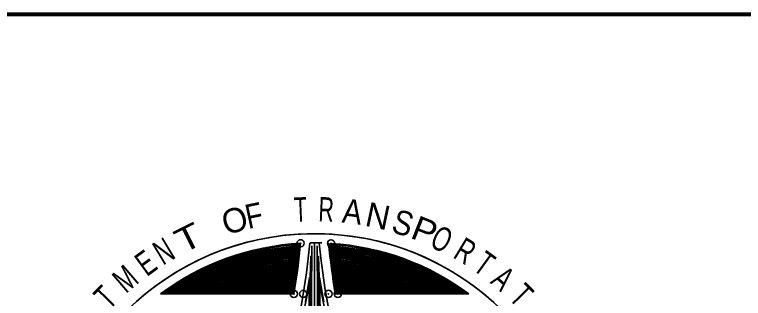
# Model space of a CAD drawing. Extents: x 763.8 to 797.8, y -170.3 to -127.3.
# Drawn here: x 779.152 to 783.061, y -128.791 to -127.265 of the extents above; entities that cross this region are included whole.
import ezdxf
from ezdxf.enums import TextEntityAlignment as Align

# ---------------------------------------------------------------- set-up
doc = ezdxf.new("R2010")
doc.units = 0
doc.header["$LTSCALE"] = 0.077
doc.header["$PDMODE"] = 32
doc.header["$PDSIZE"] = 0.0385
doc.layers.add('1', color=7, linetype='Continuous', lineweight=35)

msp = doc.modelspace()

# ---------------------------------------------------------------- linework, layer by layer
at = {"layer": '1', "lineweight": 80}
msp.add_line((794.76075, -127.26542), (766.76075, -127.26542), dxfattribs=at)
at = {"layer": '1'}
for p, q in [((780.76075, -128.49192), (780.76075, -130.44333)), ((780.6495, -128.76592), (779.93417, -128.76592)), ((780.87192, -128.76592), (781.58725, -128.76592))]:
    msp.add_line(p, q, dxfattribs=at)
for points in [[(779.95233, -128.76325), (780.64367, -128.76075), (780.6815, -128.49958), (780.57933, -128.51033), (780.46733, -128.53008), (780.35692, -128.55892), (780.27125, -128.58775), (780.20117, -128.61408), (780.14183, -128.64625), (780.07592, -128.67842), (780.01992, -128.71708), (779.97375, -128.74433), (779.94575, -128.76408), (779.95975, -128.75992), (780.63867, -128.7575), (780.67742, -128.50617), (780.57933, -128.51775), (780.47475, -128.535), (780.38983, -128.55808), (780.361, -128.563), (780.26875, -128.59517), (780.21025, -128.61658), (780.07842, -128.685), (779.96308, -128.75833), (780.63625, -128.7525), (780.67333, -128.51192), (780.56208, -128.52675), (780.478, -128.53917), (780.36592, -128.56633), (780.21517, -128.6215), (780.08083, -128.68908), (779.97708, -128.75583), (780.63125, -128.75008), (780.66917, -128.51692), (780.48217, -128.54325), (780.37258, -128.57125), (780.22008, -128.62567), (780.08417, -128.694), (779.99025, -128.75342), (780.62633, -128.74592), (780.66508, -128.52183), (780.48375, -128.54817), (780.37092, -128.577), (780.22342, -128.63058), (780.08583, -128.69817), (780.0075, -128.74925), (780.62225, -128.7435), (780.65925, -128.52842), (780.48958, -128.55317), (780.37008, -128.58283), (780.22917, -128.6355), (780.08825, -128.70225), (780.02233, -128.74758), (780.61725, -128.73933), (780.65267, -128.535), (780.49283, -128.55892), (780.37417, -128.58858), (780.23742, -128.63883), (780.09158, -128.708), (780.03717, -128.7435), (780.61317, -128.73525), (780.64858, -128.54242), (780.49775, -128.56383), (780.37917, -128.5935), (780.24233, -128.64292), (780.09483, -128.713), (780.0545, -128.74017), (780.60817, -128.73108), (780.64442, -128.549), (780.50358, -128.56958), (780.38242, -128.59933), (780.24567, -128.64875), (780.0965, -128.71708), (780.07017, -128.73692), (780.60408, -128.727), (780.6395, -128.55558), (780.50358, -128.57542), (780.38658, -128.60508), (780.24892, -128.65367), (780.099, -128.72292), (780.0825, -128.73358), (780.59833, -128.72208), (780.63458, -128.56142), (780.5085, -128.58117), (780.39067, -128.60917), (780.25225, -128.65942), (780.09817, -128.73108), (780.59417, -128.71958), (780.628, -128.56883), (780.51342, -128.58692), (780.3915, -128.61742), (780.2605, -128.66275), (780.11792, -128.72783), (780.59092, -128.71708), (780.62225, -128.57625), (780.52, -128.591), (780.39067, -128.62483), (780.26708, -128.666), (780.13692, -128.7245), (780.58758, -128.71383), (780.61725, -128.58442)], [(781.56917, -128.76325), (780.87783, -128.76075), (780.83992, -128.49958), (780.94208, -128.51033), (781.05417, -128.53008), (781.16458, -128.55892), (781.25025, -128.58775), (781.32025, -128.61408), (781.37967, -128.64625), (781.44558, -128.67842), (781.50158, -128.71708), (781.54775, -128.74433), (781.57575, -128.76408), (781.56175, -128.75992), (780.88275, -128.7575), (780.84408, -128.50617), (780.94208, -128.51775), (781.04675, -128.535), (781.13158, -128.55808), (781.16042, -128.563), (781.25275, -128.59517), (781.31125, -128.61658), (781.44308, -128.685), (781.55842, -128.75833), (780.88525, -128.7525), (780.84817, -128.51192), (780.95942, -128.52675), (781.04342, -128.53917), (781.1555, -128.56633), (781.30625, -128.6215), (781.44058, -128.68908), (781.54442, -128.75583), (780.89017, -128.75008), (780.85225, -128.51692), (781.03933, -128.54325), (781.14892, -128.57125), (781.30133, -128.62567), (781.43725, -128.694), (781.53125, -128.75342), (780.89517, -128.74592), (780.85642, -128.52183), (781.03767, -128.54817), (781.15058, -128.577), (781.29808, -128.63058), (781.43567, -128.69817), (781.51392, -128.74925), (780.89925, -128.7435), (780.86217, -128.52842), (781.03192, -128.55317), (781.15142, -128.58283), (781.29225, -128.6355), (781.43317, -128.70225), (781.49908, -128.74758), (780.90417, -128.73933), (780.86875, -128.535), (781.02858, -128.55892), (781.14725, -128.58858), (781.28408, -128.63883), (781.42992, -128.708), (781.48425, -128.7435), (780.90833, -128.73525), (780.87292, -128.54242), (781.02367, -128.56383), (781.14233, -128.5935), (781.27908, -128.64292), (781.42658, -128.713), (781.467, -128.74017), (780.91325, -128.73108), (780.877, -128.549), (781.01792, -128.56958), (781.139, -128.59933), (781.27583, -128.64875), (781.42492, -128.71708), (781.45133, -128.73692), (780.91742, -128.727), (780.88192, -128.55558), (781.01792, -128.57542), (781.13492, -128.60508), (781.2725, -128.65367), (781.4225, -128.72292), (781.43892, -128.73358), (780.92317, -128.72208), (780.88692, -128.56142), (781.013, -128.58117), (781.13075, -128.60917), (781.26925, -128.65942), (781.42325, -128.73108), (780.92725, -128.71958), (780.8935, -128.56883), (781.008, -128.58692), (781.13, -128.61742), (781.261, -128.66275), (781.4035, -128.72783), (780.93058, -128.71708), (780.89925, -128.57625), (781.00142, -128.591), (781.13075, -128.62483), (781.25442, -128.666), (781.38458, -128.7245), (780.93383, -128.71383), (780.90417, -128.58442)], [(780.74633, -128.50825), (780.73367, -130.434)], [(780.77517, -128.50825), (780.78775, -130.434)], [(780.70525, -128.85233), (780.72108, -128.77025), (780.73683, -128.67867), (780.74, -128.565), (780.74, -128.75133), (780.71475, -130.42142)], [(780.81617, -128.85233), (780.80042, -128.77025), (780.78458, -128.67867), (780.7815, -128.565), (780.7815, -128.75133), (780.80675, -130.42142)], [(780.61725, -128.58442), (780.52742, -128.596), (780.39808, -128.62892), (780.27367, -128.67017), (780.15833, -128.72125), (780.5835, -128.7105), (780.6115, -128.59025), (780.52908, -128.60342), (780.40875, -128.63225), (780.27533, -128.67592), (780.18225, -128.71708), (780.5785, -128.70558), (780.60658, -128.59842), (780.41042, -128.63717), (780.20442, -128.71383), (780.57358, -128.70225), (780.60492, -128.596), (780.53242, -128.61), (780.417, -128.63475), (780.28192, -128.68), (780.21517, -128.70967), (780.5695, -128.69733), (780.59833, -128.60667), (780.41375, -128.64292), (780.24075, -128.70725), (780.5645, -128.694), (780.59333, -128.61242), (780.41375, -128.6495), (780.26958, -128.70308), (780.56125, -128.68992), (780.58758, -128.61908), (780.41458, -128.6545), (780.29508, -128.70067), (780.55792, -128.68658), (780.57933, -128.6265), (780.417, -128.65942), (780.32308, -128.69733), (780.55383, -128.68333), (780.57192, -128.63475), (780.422, -128.66442), (780.35192, -128.69242), (780.55217, -128.68), (780.56533, -128.64217), (780.42283, -128.6685), (780.37833, -128.68825), (780.54558, -128.67675), (780.56042, -128.64792), (780.42525, -128.67342), (780.39975, -128.68417), (780.54142, -128.67425), (780.55217, -128.65617), (780.42442, -128.67925), (780.54067, -128.67017), (780.54392, -128.66192), (780.48875, -128.67258), (780.539, -128.66933)], [(780.90417, -128.58442), (780.994, -128.596), (781.12333, -128.62892), (781.24775, -128.67017), (781.36317, -128.72125), (780.938, -128.7105), (780.91, -128.59025), (780.99233, -128.60342), (781.11267, -128.63225), (781.24617, -128.67592), (781.33925, -128.71708), (780.94292, -128.70558), (780.91492, -128.59842), (781.111, -128.63717), (781.317, -128.71383), (780.94783, -128.70225), (780.91658, -128.596), (780.98908, -128.61), (781.10442, -128.63475), (781.23958, -128.68), (781.30625, -128.70967), (780.952, -128.69733), (780.92317, -128.60667), (781.10775, -128.64292), (781.28075, -128.70725), (780.95692, -128.694), (780.92808, -128.61242), (781.10775, -128.6495), (781.25192, -128.70308), (780.96025, -128.68992), (780.93383, -128.61908), (781.10692, -128.6545), (781.22633, -128.70067), (780.9635, -128.68658), (780.94208, -128.6265), (781.10442, -128.65942), (781.19833, -128.69733), (780.96767, -128.68333), (780.9495, -128.63475), (781.0995, -128.66442), (781.1695, -128.69242), (780.96925, -128.68), (780.95608, -128.64217), (781.09867, -128.6685), (781.14317, -128.68825), (780.97592, -128.67675), (780.96108, -128.64792), (781.09617, -128.67342), (781.12175, -128.68417), (780.98, -128.67425), (780.96925, -128.65617), (781.097, -128.67925), (780.98083, -128.67017), (780.9775, -128.66192), (781.03275, -128.67258), (780.9825, -128.66933)], [(780.71158, -128.80808), (780.73367, -128.67867), (780.70217, -130.41508)], [(780.80983, -128.80808), (780.78775, -128.67867), (780.81933, -130.41508)]]:
    msp.add_lwpolyline(points, dxfattribs=at)
for centre, radius, start, end in [((780.76073, -129.87583), 1.43338, 0, 351.33483), ((780.76073, -129.87583), 1.43338, 45, 36.33483), ((776.63402, -128.08937), 4.1216, 318.80967, 354.36889), ((780.76073, -129.87583), 1.38388, 93.09724, 126.67524), ((776.63402, -128.08937), 4.0721, 350.43639, 354.29765), ((780.76073, -129.87583), 1.38388, 88.41037, 91.03641), ((780.76073, -129.87583), 1.38388, 88.41037, 91.03641), ((784.88744, -128.08937), 4.1216, 185.63111, 221.19033), ((784.88744, -128.08937), 4.0721, 185.70235, 189.56361), ((780.76073, -129.87583), 1.38388, 53.32476, 86.34208)]:
    msp.add_arc(centre, radius, start, end, dxfattribs=at)
for p in [(780.68592, -128.494), (780.849, -128.49475), (780.6495, -128.76592), (780.69975, -128.76592), (780.83525, -128.76592), (780.88542, -128.76592)]:
    msp.add_point(p, dxfattribs=at)

# ---------------------------------------------------------------- texts
for s, rotation, width, p in [('T', 2.496, 0.65, (780.68849, -128.37746)), ('R', 357.519, 0.65, (780.8203, -128.37724)), ('A', 352.685, 0.9, (780.95593, -128.38841)), ('F', 12.026, 0.85, (780.44947, -128.40856)), ('S', 343.097, 0.9, (781.21625, -128.44756)), ('T', 26.479, 1.25, (780.11249, -128.52287)), ('P', 338.561, 1.1, (781.32766, -128.48697)), ('O', 333.616, 0.7, (781.41427, -128.53)), ('N', 30.987, 0.7, (779.98493, -128.59214)), ('R', 328.804, 0.7, (781.53559, -128.59133)), ('E', 35.983, 0.7, (779.89374, -128.65218)), ('T', 324.111, 0.7, (781.63368, -128.65619)), ('M', 40.52, 0.7, (779.78752, -128.73416)), ('A', 319.165, 0.7, (781.72973, -128.73223)), ('T', 45.435, 0.7, (779.6857, -128.82998)), ('T', 314.64, 0.7, (781.82431, -128.81815))]:
    msp.add_text(s, height=0.1307, rotation=rotation, dxfattribs=dict(at, width=width)).set_placement(p, align=Align.CENTER)
for s, rotation, p in [('O', 16.608, (780.35078, -128.43261)), ('N', 348.052, (781.08726, -128.41191))]:
    msp.add_text(s, height=0.1307, rotation=rotation, dxfattribs=at).set_placement(p, align=Align.CENTER)

doc.saveas('drawing.dxf')
